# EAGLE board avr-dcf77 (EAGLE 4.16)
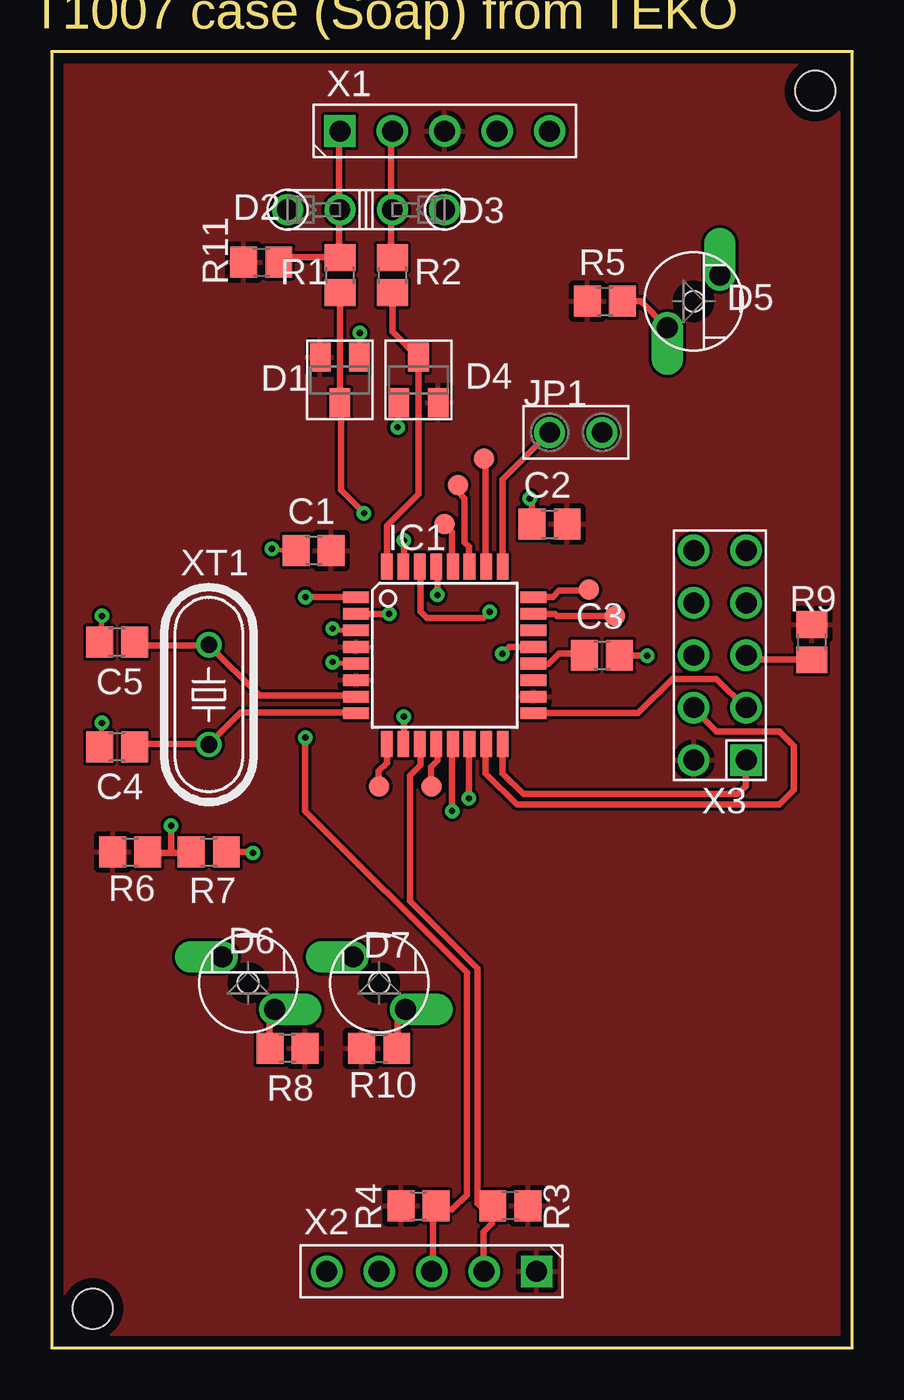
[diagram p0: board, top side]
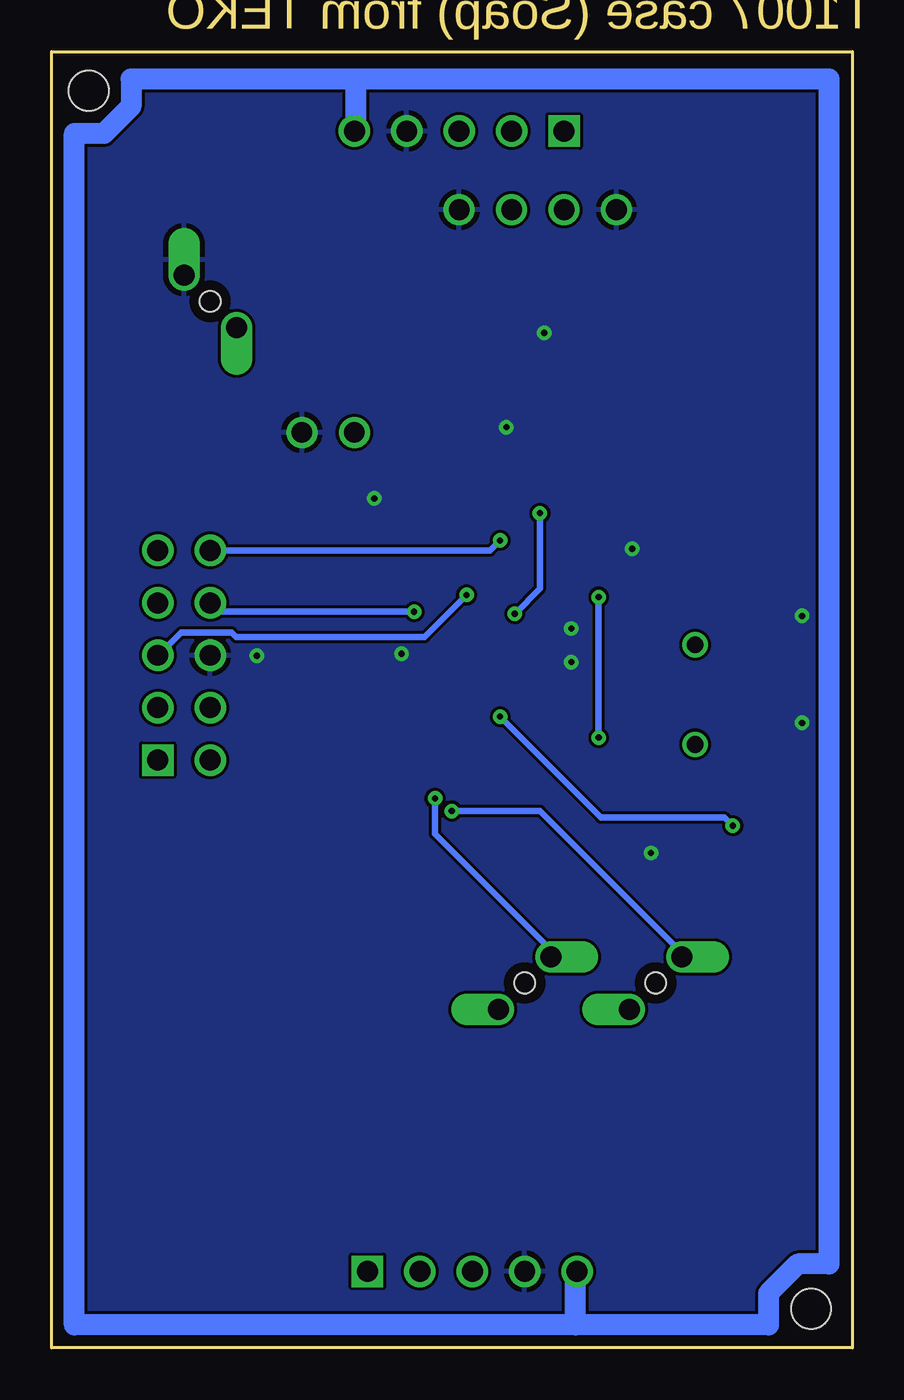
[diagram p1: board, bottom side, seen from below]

Size 38.8 x 62.8 mm. Coordinates in mm from the lower left corner, seen from the top.
Outline: 0,0 38.8,0 38.8,62.8 0,62.8 0,0
Copper layers (1*16): Top 0.035mm / dielectric 1.5mm / Bottom 0.035mm
Design rules "pcpPool2Lagen": minimum track width 0.15mm, minimum drill 0.3mm, track to track 0.15mm, track to pad 0.15mm, pad to pad 0.15mm, via to via 0.15mm, smd to smd 2mil, copper to edge 0.5mm, drill to drill 0.25mm, minimum pad ring 0.2mm, minimum via ring 0.2mm, stop-mask expansion 0mil, vias tented up to drill 0.35mm, thermal gap 0.25mm
Holes 1.93 mm at 2,1.9 37,60.9

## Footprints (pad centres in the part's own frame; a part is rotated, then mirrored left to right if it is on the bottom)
C0805 = smd 1.3 x 1.5: 1 -0.85,0; 2 0.85,0
SOT23 = smd 1 x 1.4: 1 0.95,-1.1; 2 -0.95,-1.1; 3 0,1.1
DIODE1 = drill 1 round: 1 -1.27,0; 2 1.27,0
LED2 = drill 1.016 offset: ANODE -1.27,1.27; CATHODE 1.27,-1.27 | hole 1: 0,0
TQFP32 = smd 1.27 x 0.559: 1 -4.293,2.8; 2 -4.293,2; 3 -4.293,1.2; 4 -4.293,0.4; 5 -4.293,-0.4; 6 -4.293,-1.2; 7 -4.293,-2; 8 -4.293,-2.8; 17 4.293,-2.8; 18 4.293,-2; 19 4.293,-1.2; 20 4.293,-0.4; 21 4.293,0.4; 22 4.293,1.2; 23 4.293,2; 24 4.293,2.8 | smd 0.559 x 1.27: 9 -2.8,-4.293; 10 -2,-4.293; 11 -1.2,-4.293; 12 -0.4,-4.293; 13 0.4,-4.293; 14 1.2,-4.293; 15 2,-4.293; 16 2.8,-4.293; 25 2.8,4.293; 26 2,4.293; 27 1.2,4.293; 28 0.4,4.293; 29 -0.4,4.293; 30 -1.2,4.293; 31 -2,4.293; 32 -2.8,4.293
HEADER_1X2_2_54 = drill 1 round: 1 -1.27,0; 2 1.27,0
R0805 = smd 1.3 x 1.5: 1 -0.85,0; 2 0.85,0
TEP10 = smd 1 x 1: 1 0,0
PINS05 = drill 1.016 square: 1 -5.08,0 | drill 1.016 round: 2 -2.54,0; 3 0,0; 4 2.54,0; 5 5.08,0
HEADER_2X5_2_54 = drill 1.016 square: 1 -5.08,-1.27 | drill 1.016 round: 2 -5.08,1.27; 3 -2.54,-1.27; 4 -2.54,1.27; 5 0,-1.27; 6 0,1.27; 7 2.54,-1.27; 8 2.54,1.27; 9 5.08,-1.27; 10 5.08,1.27
HC49/S = drill 0.813 round: 1 -2.413,0; 2 2.413,0

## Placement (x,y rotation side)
C1  100N  [C0805]  12.7,38.63 0 top
C2  100N  [C0805]  24.13,39.91 0 top
C3  100N  [C0805]  26.67,33.55 0 top
C4  27P  [C0805]  3.17,29.11 180 top
C5  27P  [C0805]  3.17,34.19 180 top
D1  BAV99  [SOT23]  13.97,46.89 180 top
D2  Z3V6  [DIODE1]  12.7,55.14 180 top
D3  Z3V6  [DIODE1]  17.78,55.14 0 top
D4  BAV99  [SOT23]  17.78,46.89 0 top
D5  LED2  [LED2]  31.11,50.7 90 top
D6  LED2  [LED2]  9.53,17.68 180 top
D7  LED2  [LED2]  15.88,17.68 180 top
IC1  ATMEGA8/TQFP32  [TQFP32]  19.05,33.55 0 top
JP1  JUMPER  [HEADER_1X2_2_54]  25.4,44.35 0 top
R1  68R  [R0805]  13.97,51.97 270 top
R2  68R  [R0805]  16.51,51.97 270 top
R3  10K  [R0805]  22.23,6.89 180 top
R4  10K  [R0805]  17.78,6.89 0 top
R5  360R  [R0805]  26.81,50.7 0 top
R6  10K  [R0805]  3.81,24.03 0 top
R7  10K  [R0805]  7.62,24.03 0 top
R8  360R  [R0805]  11.43,14.51 180 top
R9  10K  [R0805]  36.83,34.19 270 top
R10  360R  [R0805]  15.88,14.51 0 top
R11  2k2  [R0805]  10.16,52.6 0 top
T1  P1  [TEP10]  15.88,27.2 0 top
T2  P1  [TEP10]  18.41,27.2 0 top
T3  P1  [TEP10]  26.04,36.73 0 top
T4  P1  [TEP10]  20.95,43.08 0 top
T5  P1  [TEP10]  27.3,35.46 0 top
T6  P1  [TEP10]  19.05,39.91 0 top
T8  P1  [TEP10]  19.68,41.81 0 top
X1  SIL5  [PINS05]  19.05,58.95 0 top
X2  5PIN  [PINS05]  18.41,3.71 180 top
X3  HEADER10  [HEADER_2X5_2_54]  32.38,33.55 90 top
XT1  12MHZ  [HC49/S]  7.62,31.65 90 top

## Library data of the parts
C1-C5 D1-D7 IC1 JP1 R1-R11 T1-T6 T8 X1-X3 XT1 = avr-dcf77

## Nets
AREF: C3.1 IC1.20
DCF_IN: IC1.11 R3.2 X2.2
DCF_IRQ: IC1.1 R4.2 X2.3
GND: C1.1 C2.1 C3.2 C4.2 C5.2 D1.2 D2.2 D3.2 D4.2 D5.CATHODE IC1.3 IC1.5 IC1.21 JP1.2 R7.2 X1.4 X2.4 X3.6
LED2H: D6.ANODE R8.2
LED3H: D7.ANODE R10.2
LEDH: D5.ANODE R5.2
RES1: IC1.12 T2.1
RES4: IC1.23 T5.1
RES5: IC1.24 T3.1
RES7: IC1.26 T4.1
RES8: IC1.27 T8.1
RES9: IC1.28 T6.1
RES10: IC1.9 T1.1
RXD: IC1.30 X3.8
S_MISO: IC1.16 X3.1
S_MOSI: IC1.15 X3.4
S_RST: IC1.29 R9.2 X3.5
S_SCK: IC1.17 X3.3
SECONDS: D7.CATHODE IC1.14
SHIELD: X1.5 X2.5
THRESHOLD: IC1.10 R6.2 R7.1
TIME: D6.CATHODE IC1.13
TXD: IC1.31 X3.10
USB_M: D1.3 IC1.2 R1.2
USB_M_RAW: D2.1 R1.1 R11.2 X1.1
USB_P: D4.3 IC1.32 R2.2
USB_P_RAW: D3.1 R2.1 X1.2
USBBOOT#: IC1.25 JP1.1
VCC: C1.2 C2.2 D1.1 D4.1 IC1.4 IC1.6 IC1.18 R3.1 R4.1 R5.1 R6.1 R8.1 R9.1 R10.1 R11.1 X1.3 X2.1 X3.2
XTAL1_CPU: C5.1 IC1.7 XT1.2
XTAL2_CPU: C4.1 IC1.8 XT1.1

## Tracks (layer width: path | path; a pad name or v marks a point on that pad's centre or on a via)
AREF
  Top 0.305: IC1.20 23.37,33.12 24.08,33.12 24.59,33.63 25.9,33.63 | 25.9,33.63 25.91,33.63 | 25.9,33.63 C3.1
DCF_IN
  Top 0.305: 20.93,3.69 20.93,3.66 | X2.2 20.93,3.69 | 20.93,3.69 20.93,5.63 21.34,6.04 R3.2 21.02,6.61 21.03,6.61 20.62,7.01 20.62,18.39 17.37,21.64 17.37,27.74 17.88,28.25 17.88,29.26 IC1.11
DCF_IRQ  (via drill 0.3)
  Top 0.305: X2.3 18.47,3.66 18.49,3.66 18.49,6.59 R4.2 18.45,6.71 19.41,6.71 20.12,7.42 20.12,18.19 12.29,26.01 v12.29,29.57 | IC1.1 14.74,36.37 v12.29,36.37
  Bottom 0.305: v12.29,29.57 v12.29,36.37
GND  (via drill 0.3)
  Top 0.254: IC1.3 13.92,34.75 v13.61,34.85 | IC1.5 13.92,33.16 v13.61,33.23 | C1.1 11.18,38.63 v10.67,38.71 | C5.2 2.44,34.3 v2.44,35.46 | C4.2 2.44,29.22 v2.44,30.28 | D4.2 16.87,45.75 v16.76,44.6 | D1.2 14.94,48 v14.94,49.18
  Top 0.305: C2.1 23.28,41.03 v23.16,41.15 | IC1.21 22.17,33.95 v21.84,33.63 | C3.2 28.83,33.55 v28.85,33.53 | R7.2 9.7,24.03 v9.75,23.98
  pour Bottom: 0.2,0.2 38.61,0.2 38.51,62.59 0.1,62.69
LED2H
  Top 0.305: R8.2 10.57,14.52 10.57,16.18 D6.ANODE
LED3H
  Top 0.305: R10.2 16.76,14.54 16.76,16.05 17.17,16.46 17.17,16.43 D7.ANODE
LEDH
  Top 0.305: R5.2 28.55,50.7 29.77,49.48 D5.ANODE
RES1
  Top 0.305: IC1.12 18.69,29.22 18.69,28.45 18.39,28.14 18.39,27.18 | 18.39,27.18 18.39,27.13 | T2.1 18.39,27.18
RES4
  Top 0.305: IC1.23 24.38,35.56 24.49,35.46 T5.1 27.33,35.46
RES5
  Top 0.305: IC1.24 23.36,36.37 24.28,36.37 24.59,36.68 26.01,36.68 26.01,36.7 T3.1
RES7
  Top 0.305: T4.1 21.03,42.98 21.03,37.87 IC1.26
RES8
  Top 0.305: IC1.27 20.22,37.88 20.22,38.81 20.02,39.02 20.02,41.15 19.71,41.45 19.71,41.84 | 19.71,41.84 19.71,41.86 | 19.71,41.84 T8.1
RES9
  Top 0.305: IC1.28 19.41,37.89 19.41,39.52 19.02,39.91 | 19.02,39.91 19,39.93 | 19.02,39.91 T6.1
RES10
  Top 0.305: IC1.9 16.26,28.35 15.85,27.94 15.85,27.23 T1.1
RXD  (via drill 0.3)
  Top 0.305: IC1.30 17.88,37.82 17.88,35.66 18.19,35.36 20.93,35.36 v21.23,35.66
  Bottom 0.305: v21.23,35.66 30.68,35.66 X3.8
S_MISO
  Top 0.305: IC1.16 21.85,27.83 22.86,26.82 33.22,26.82 33.63,27.23 33.63,28.45 X3.1
S_MOSI
  Top 0.305: IC1.15 21.03,29.24 21.03,27.84 22.55,26.32 35.26,26.32 35.97,27.03 35.97,29.16 35.26,29.87 32.21,29.87 31.09,30.99 X3.4
S_RST  (via drill 0.3)
  Top 0.305: R9.2 33.82,33.34 33.63,33.53 X3.5 | IC1.29 18.69,37.8 v18.69,36.48
  Bottom 0.305: v18.69,36.48 20.73,34.44 29.87,34.44 30.07,34.65 32.51,34.65 33.63,33.53 X3.5
S_SCK
  Top 0.305: IC1.17 28.42,30.75 30.07,32.41 32.21,32.41 33.63,30.99 X3.3
SECONDS  (via drill 0.3)
  Top 0.305: IC1.14 20.22,29.26 v20.22,26.62
  Bottom 0.305: v20.22,26.62 20.22,24.89 14.61,19.28 D7.CATHODE
SHIELD
  Bottom 1.016: X1.5 24.08,59.01 24.08,61.47 | 13.41,1.12 4.06,1.12 4.06,2.64 2.64,4.07 1.12,4.07 1.12,61.47 24.08,61.47 | 13.41,1.12 37.69,1.12 37.69,58.83 36.27,58.83 34.95,60.15 34.95,61.47 24.08,61.47 | X2.5 13.41,3.63 13.41,1.12
THRESHOLD  (via drill 0.3)
  Top 0.305: IC1.10 17.07,29.28 v17.07,30.58 | 5.79,23.98 v5.79,25.3 | 4.61,23.98 4.47,23.98 | R6.2 4.61,23.98 | 4.61,23.98 5.79,23.98 | 6.82,23.98 6.91,23.98 | 6.82,23.98 R7.1 | 5.79,23.98 6.82,23.98
  Bottom 0.305: v17.07,30.58 12.19,25.71 6.2,25.71 v5.79,25.3
TIME  (via drill 0.3)
  Top 0.305: 19.41,29.31 19.41,29.36 | 19.41,29.31 IC1.13 | v19.41,26.01 19.41,29.31
  Bottom 0.305: v19.41,26.01 15.14,26.01 8.23,19.1 8.26,19.08 D6.CATHODE
TXD  (via drill 0.3)
  Top 0.305: IC1.31 17.05,37.88 17.07,37.9 v17.07,39.12
  Bottom 0.305: X3.10 17.55,38.63 v17.07,39.12
USB_M  (via drill 0.3)
  Top 0.305: 13.97,45.77 D1.3 | 13.97,45.77 R1.2 | 13.97,45.77 14.02,45.72 14.02,41.56 v15.14,40.44 | IC1.2 14.74,35.55 14.73,35.56 v16.36,35.56
  Bottom 0.305: v15.14,40.44 15.14,36.78 v16.36,35.56
USB_M_RAW
  Top 0.305: 13.92,55.14 13.92,55.07 | X1.1 13.92,58.95 13.92,55.14 | 13.92,52.82 13.92,52.63 | 13.92,52.82 R1.1 13.96,52.83 13.92,52.83 | 13.92,55.14 D2.1 | 13.92,52.83 13.92,52.82 | 13.92,52.83 13.92,55.14 | R11.2 11.24,52.83 13.92,52.83
USB_P
  Top 0.305: R2.2 16.51,49.23 17.78,47.96 D4.3 17.78,41.35 16.26,39.83 16.26,37.9 16.25,37.89 IC1.32
USB_P_RAW
  Top 0.305: 16.46,55.14 16.46,55.07 | X1.2 16.46,58.95 16.46,55.14 | 16.46,52.82 16.46,52.63 | R2.1 16.46,52.82 | 16.46,55.14 D3.1 | 16.46,52.82 16.46,55.14
USBBOOT#
  Top 0.305: IC1.25 21.84,42.06 JP1.1 24.18,44.4
VCC
  pour Top: 0,-0.1 38.81,-0.1 38.81,62.79 0,62.79
XTAL1_CPU
  Top 0.305: 7.64,34.04 7.72,34.04 | 7.64,34.04 XT1.2 10.08,31.6 14.8,31.6 | C5.1 4.18,34.04 7.64,34.04 | 14.8,31.6 14.83,31.6 | 14.8,31.6 IC1.7
XTAL2_CPU
  Top 0.305: C4.1 4.18,29.26 7.62,29.26 XT1.1 9.17,30.79 14.79,30.79 | 14.79,30.79 14.94,30.79 | 14.79,30.79 IC1.8

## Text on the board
Dimension: T1007 case (Soap) from TEKO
